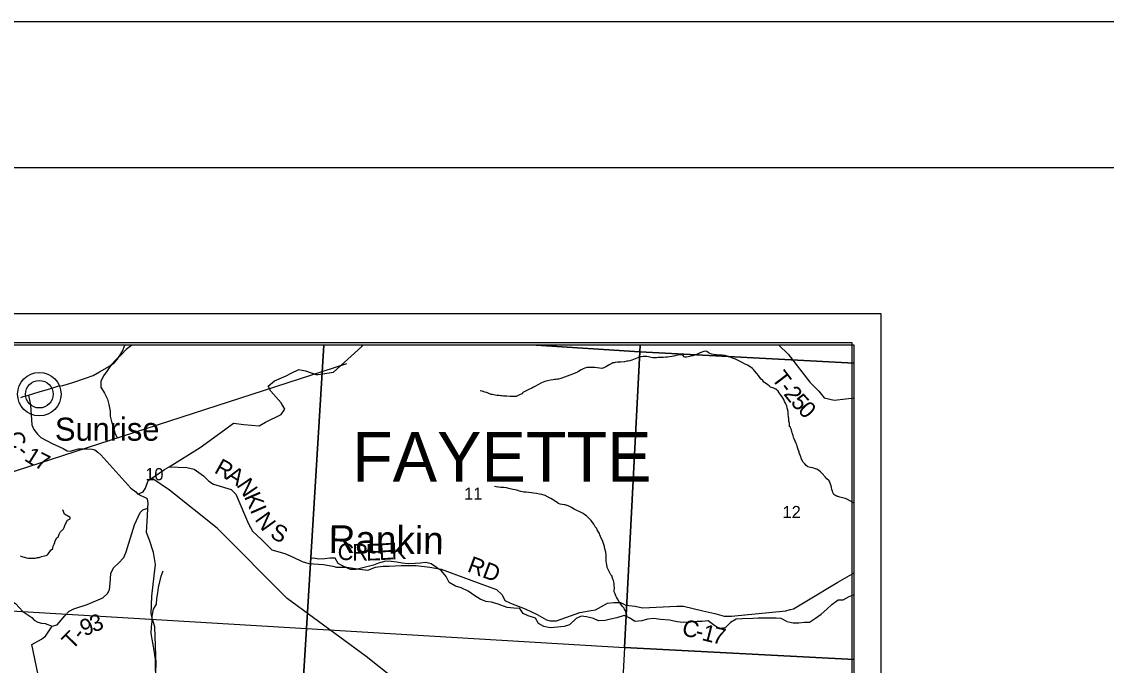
# Model space of a CAD drawing. Extents: x 0 to 34, y 0 to 22.
# Drawn here: x 6.056 to 9.772, y 19.794 to 22 of the extents above; entities that cross this region are included whole.
import ezdxf

# ---------------------------------------------------------------- set-up
doc = ezdxf.new("R2010")
doc.units = 0
for name, color, linetype in [('GM_X_County', 7, 'Continuous'), ('GM_X_County_Road', 7, 'Continuous'), ('GM_X_County_Road_Text', 7, 'Continuous'), ('GM_X_Minor_River', 7, 'Continuous'), ('GM_X_Minor_River_Text', 7, 'Continuous'), ('GM_X_Section', 7, 'Continuous'), ('GM_X_Section_Text', 7, 'Continuous'), ('GM_X_State_Route', 7, 'Continuous'), ('GM_X_Township', 7, 'Continuous'), ('GM_X_Township_Road', 7, 'Continuous'), ('GM_X_Township_Road_Text', 7, 'Continuous'), ('GM_X_Township_ROW', 7, 'Continuous'), ('GM_X_Township_Text', 7, 'Continuous'), ('GM_X_Unincorporated', 7, 'Continuous'), ('GM_X_Unincorporated_Location', 7, 'Continuous'), ('GM_X_Unincorporated_Text', 7, 'Continuous'), ('GM_X_US_Route', 7, 'Continuous'), ('SH_Border', 7, 'Continuous'), ('SH_Cut_Line', 7, 'Continuous'), ('SH_Data', 7, 'Continuous')]:
    doc.layers.add(name, color=color, linetype=linetype)

msp = doc.modelspace()

# ---------------------------------------------------------------- linework, layer by layer
at = {"layer": 'GM_X_County'}
msp.add_lwpolyline([(8.9084, 15.63), (8.9084, 20.8908), (2.1084, 20.8908), (2.1084, 19.9847)], dxfattribs=at)
at = {"layer": 'GM_X_County_Road'}
for points in [[(6.0801, 20.7202), (6.0863, 20.6856), (6.0907, 20.6183), (6.098, 20.6017), (6.1099, 20.5867), (6.1223, 20.5747), (6.1612, 20.5542), (6.1985, 20.537), (6.212, 20.5297), (6.2223, 20.5284), (6.2514, 20.5358), (6.2809, 20.5358), (6.298, 20.5354), (6.307, 20.5328), (6.3168, 20.5251), (6.3277, 20.5153), (6.4298, 20.4016), (6.4468, 20.3888), (6.4546, 20.3811), (6.4725, 20.3888), (6.4764, 20.3948), (6.477, 20.3957)], [(6.477, 20.3957), (6.481, 20.4016), (6.4895, 20.4272), (6.5017, 20.4356), (6.545, 20.4656), (6.5621, 20.4742), (6.6216, 20.4724), (6.6469, 20.466), (6.6786, 20.4438), (6.6976, 20.4248), (6.7135, 20.4153), (6.7737, 20.3963), (6.7895, 20.3805), (6.8339, 20.2791), (6.8465, 20.2538), (6.8782, 20.2253), (6.8972, 20.2063), (6.9131, 20.1904), (6.9574, 20.1777), (6.986, 20.1651), (7.0177, 20.1493), (7.0398, 20.1429), (7.0905, 20.1397), (7.1222, 20.1334), (7.1349, 20.1302), (7.1697, 20.1302), (7.2141, 20.1239), (7.2426, 20.1207), (7.268, 20.1302), (7.2933, 20.1334), (7.3155, 20.1334), (7.3567, 20.1365), (7.4074, 20.1365), (7.4549, 20.1302), (7.493, 20.1239), (7.6197, 20.0763), (7.6831, 20.0542), (7.7021, 20.0352), (7.7116, 20.0162), (7.7306, 20.0066), (7.7813, 19.9876), (7.8225, 19.9686), (7.8542, 19.9496), (7.8669, 19.9465), (7.8891, 19.9464), (7.9683, 19.975), (8, 19.9813), (8.0221, 19.9845), (8.0633, 20.0066), (8.0855, 20.0098), (8.1077, 20.0098), (8.1267, 20.0003), (8.1584, 19.9971), (8.1837, 19.9908), (8.301, 19.9971), (8.3232, 19.9971), (8.3897, 19.9813), (8.4309, 19.9718), (8.4626, 19.9622), (8.4879, 19.9622), (8.5228, 19.9654), (8.6741, 19.981), (8.6894, 19.9849), (8.6898, 19.985)], [(6.5144, 19.7584), (6.5165, 19.7955), (6.5124, 19.9254), (6.5041, 19.9522), (6.5, 19.9708), (6.5021, 20.0306), (6.5103, 20.1007), (6.5145, 20.1399), (6.5083, 20.1811), (6.4938, 20.2224), (6.4835, 20.2492), (6.4877, 20.3069), (6.4889, 20.3331), (6.4897, 20.3502), (6.4877, 20.3647), (6.4546, 20.3811)], [(8.6898, 19.985), (8.701, 19.9878), (8.7464, 20.0156), (8.852, 20.0788), (8.9084, 20.1115)]]:
    msp.add_lwpolyline(points, dxfattribs=at)
at = {"layer": 'GM_X_Minor_River'}
for points in [[(6.4328, 20.8908), (6.4327, 20.8907), (6.4144, 20.8764), (6.3985, 20.859), (6.381, 20.8431), (6.3627, 20.8234), (6.349, 20.8037), (6.3368, 20.7863), (6.3269, 20.7666), (6.3276, 20.7476), (6.3404, 20.7271), (6.3501, 20.7058), (6.3553, 20.6876), (6.3598, 20.6655), (6.3597, 20.6481), (6.3642, 20.6299), (6.3709, 20.6086), (6.3754, 20.5896), (6.3829, 20.5744)], [(8.6519, 20.7275), (8.6475, 20.7336), (8.64, 20.7406), (8.6329, 20.7434), (8.6257, 20.7462), (8.622, 20.7477), (8.6182, 20.7505), (8.6126, 20.7551), (8.6044, 20.7613), (8.5992, 20.7648), (8.5958, 20.7698), (8.5899, 20.7749), (8.585, 20.7803), (8.581, 20.7868), (8.5754, 20.7945), (8.5684, 20.8026), (8.5636, 20.808), (8.5598, 20.8115), (8.5516, 20.8173), (8.5434, 20.8224), (8.5328, 20.8275), (8.5223, 20.833), (8.5133, 20.8381), (8.5017, 20.8432), (8.4915, 20.8472), (8.484, 20.85), (8.4776, 20.852), (8.4738, 20.8532), (8.4693, 20.8548), (8.4659, 20.8556), (8.4599, 20.8564), (8.4553, 20.8569), (8.4512, 20.8574), (8.4451, 20.8571), (8.4398, 20.8575), (8.4364, 20.8576), (8.4323, 20.8584), (8.427, 20.8589), (8.4206, 20.8605), (8.4168, 20.8621), (8.4119, 20.8641), (8.4078, 20.8664), (8.4037, 20.8696), (8.3988, 20.8708), (8.3938, 20.8701), (8.387, 20.8676), (8.3786, 20.8643), (8.3747, 20.8621), (8.3702, 20.8599), (8.366, 20.8577), (8.3591, 20.8555), (8.3553, 20.8548), (8.3485, 20.8534), (8.3439, 20.8523), (8.3401, 20.8513), (8.3344, 20.8506), (8.3291, 20.8507), (8.3257, 20.8511), (8.3224, 20.8561), (8.319, 20.8585), (8.3148, 20.8585), (8.3095, 20.8579), (8.3038, 20.8568), (8.2977, 20.8554), (8.2905, 20.854), (8.2685, 20.8498), (8.2636, 20.8499), (8.2548, 20.8493), (8.2476, 20.8491), (8.2438, 20.8487), (8.2374, 20.8485), (8.2309, 20.8478), (8.2264, 20.8475), (8.2219, 20.848), (8.2185, 20.8484), (8.2124, 20.8493), (8.2034, 20.8513), (8.1977, 20.8522), (8.1916, 20.853), (8.1856, 20.8528), (8.178, 20.851), (8.17, 20.8489), (8.1528, 20.8423), (8.1463, 20.8398), (8.1402, 20.838), (8.1342, 20.8366), (8.1296, 20.8359), (8.1212, 20.8345), (8.1087, 20.8328), (8.0974, 20.8326), (8.0894, 20.832), (8.0856, 20.8313), (8.0818, 20.8302), (8.078, 20.8284), (8.0715, 20.8247), (8.0581, 20.817), (8.0508, 20.8137), (8.0443, 20.8115), (8.0364, 20.8124), (8.0194, 20.8146), (7.9993, 20.8145)], [(7.9993, 20.8145), (7.9929, 20.8143), (7.986, 20.8125), (7.9799, 20.8099), (7.973, 20.8063), (7.9642, 20.8011), (7.9608, 20.7993), (7.9547, 20.7963), (7.9463, 20.7927), (7.9348, 20.7883), (7.9257, 20.7847), (7.9162, 20.7818), (7.9032, 20.7775), (7.8956, 20.7753), (7.8922, 20.7746), (7.8876, 20.7739), (7.8815, 20.7733), (7.877, 20.7726), (7.8675, 20.7716), (7.858, 20.7695), (7.8485, 20.7666), (7.837, 20.7619), (7.8248, 20.7549), (7.8164, 20.7505), (7.8103, 20.7475), (7.8038, 20.7442), (7.7938, 20.7394), (7.782, 20.734), (7.7778, 20.7317), (7.7736, 20.7292), (7.7712, 20.725), (7.7644, 20.7221), (7.7544, 20.7173), (7.7502, 20.7159), (7.7442, 20.7156), (7.7392, 20.7153), (7.7294, 20.7151), (7.718, 20.7161), (7.712, 20.7169), (7.7071, 20.717), (7.7025, 20.7175), (7.6984, 20.7179), (7.6919, 20.7184), (7.687, 20.7189), (7.6836, 20.7193), (7.6783, 20.7198), (7.6742, 20.7206), (7.6685, 20.7218), (7.6651, 20.7227), (7.6572, 20.7254), (7.6527, 20.7274), (7.6482, 20.7286), (7.6429, 20.7306), (7.6343, 20.7334), (7.6267, 20.7351)], [(8.9084, 20.3491), (8.9055, 20.3515), (8.8957, 20.3562), (8.886, 20.362), (8.8788, 20.366), (8.8736, 20.3672), (8.869, 20.3684), (8.8596, 20.3705), (8.854, 20.3721), (8.8506, 20.3729), (8.8468, 20.3745), (8.8427, 20.3768), (8.8389, 20.3792), (8.8349, 20.3868), (8.8346, 20.3906), (8.832, 20.3964), (8.831, 20.4036), (8.83, 20.4089), (8.8278, 20.415), (8.826, 20.4185), (8.8227, 20.4261), (8.8149, 20.4331), (8.809, 20.4404), (8.7993, 20.4512), (8.793, 20.4574), (8.7877, 20.4617), (8.7825, 20.4652), (8.7761, 20.4676), (8.7723, 20.4691), (8.7667, 20.4704), (8.7584, 20.4724), (8.7501, 20.4748), (8.7445, 20.4784), (8.7389, 20.4841), (8.7337, 20.4903), (8.7297, 20.498), (8.7267, 20.5041), (8.7253, 20.5087), (8.7231, 20.5144), (8.7203, 20.5228), (8.7199, 20.5266), (8.7177, 20.5304), (8.7156, 20.5373), (8.7127, 20.5453), (8.7116, 20.5495), (8.7094, 20.5538), (8.7062, 20.5618), (8.7033, 20.5698), (8.7011, 20.5748), (8.6997, 20.5813), (8.6965, 20.5908), (8.695, 20.5958), (8.6932, 20.6011), (8.6914, 20.6057), (8.6907, 20.6099), (8.687, 20.6122), (8.6871, 20.6191), (8.6864, 20.6236), (8.6847, 20.6309), (8.6841, 20.6396), (8.6838, 20.6434), (8.6835, 20.6484), (8.6828, 20.6525), (8.6822, 20.6605), (8.6819, 20.6643), (8.6805, 20.6716), (8.6794, 20.6754), (8.6772, 20.6819), (8.6769, 20.6853), (8.6729, 20.6922), (8.6703, 20.6983), (8.667, 20.7048), (8.6615, 20.7137), (8.6574, 20.7194), (8.6549, 20.7236), (8.6519, 20.7275)], [(8.1297, 19.9598), (8.1298, 19.9647), (8.128, 19.9724), (8.1262, 19.9766), (8.1248, 19.9804), (8.1214, 19.9854), (8.1204, 19.9896), (8.1141, 19.9965), (8.107, 20.0065), (8.103, 20.0119), (8.0975, 20.0222), (8.0938, 20.028), (8.0916, 20.0322), (8.0891, 20.0395), (8.0865, 20.046), (8.0862, 20.0494), (8.0868, 20.0589), (8.0862, 20.0672), (8.0859, 20.0729), (8.0845, 20.0802), (8.0842, 20.0844), (8.0816, 20.0897), (8.0791, 20.0966), (8.0788, 20.1), (8.0751, 20.1043), (8.0725, 20.1089), (8.0674, 20.1184), (8.0644, 20.1246), (8.0626, 20.1295), (8.0605, 20.1391), (8.0602, 20.1436), (8.0588, 20.1512), (8.0582, 20.16), (8.0585, 20.1717), (8.0571, 20.1813), (8.0547, 20.1931), (8.0529, 20.2015), (8.0497, 20.211), (8.0457, 20.2213), (8.0421, 20.2297), (8.0366, 20.2416), (8.0355, 20.2462), (8.0278, 20.2585), (8.0271, 20.2626), (8.0215, 20.2692), (8.016, 20.2776), (8.0075, 20.2899), (7.9982, 20.3), (7.9911, 20.3062), (7.9855, 20.3101), (7.9803, 20.3139), (7.9683, 20.3202), (7.9585, 20.3249), (7.9495, 20.3289), (7.9405, 20.3351), (7.9352, 20.3375), (7.9285, 20.341), (7.9251, 20.3422), (7.9217, 20.3434), (7.9183, 20.3439), (7.9145, 20.3443), (7.9085, 20.3452), (7.9017, 20.3464), (7.896, 20.3484), (7.8919, 20.3511), (7.8837, 20.357), (7.8785, 20.3605), (7.8751, 20.3624), (7.8695, 20.3656), (7.8605, 20.3707), (7.8492, 20.3762), (7.8379, 20.379), (7.83, 20.3811), (7.8198, 20.3827), (7.8096, 20.3841), (7.8031, 20.3853), (7.7937, 20.3862), (7.7846, 20.3871), (7.7767, 20.388), (7.7725, 20.3889), (7.7665, 20.3901), (7.7589, 20.3918), (7.7556, 20.393), (7.7469, 20.395), (7.7393, 20.397), (7.7341, 20.3983), (7.7258, 20.3999), (7.7175, 20.402), (7.7073, 20.4033), (7.6974, 20.4034), (7.6823, 20.406), (7.6762, 20.4065)], [(6.0505, 20.1695), (6.0569, 20.1671), (6.0603, 20.1659), (6.066, 20.1643), (6.0697, 20.1631), (6.0731, 20.1622), (6.0788, 20.161), (6.0909, 20.1608), (6.0958, 20.1611), (6.1038, 20.1617), (6.1106, 20.1631), (6.1156, 20.1638), (6.124, 20.1671), (6.1342, 20.1688), (6.1403, 20.1702), (6.1445, 20.1732), (6.1484, 20.1773), (6.1565, 20.1882), (6.1631, 20.1945), (6.1644, 20.2025), (6.1671, 20.2093), (6.1695, 20.2145), (6.1704, 20.2202), (6.177, 20.2307), (6.1808, 20.2333), (6.1844, 20.2432), (6.1876, 20.2503), (6.1957, 20.2585), (6.1999, 20.2619), (6.2019, 20.2668), (6.2027, 20.2702), (6.2054, 20.2762), (6.2137, 20.2916), (6.2221, 20.2957), (6.2218, 20.3002), (6.203, 20.3123), (6.1976, 20.3269)], [(8.6773, 19.9438), (8.6584, 19.9549), (8.641, 19.9558), (8.5796, 19.956), (8.5615, 19.9545), (8.5251, 19.9531), (8.5039, 19.9517), (8.4849, 19.9412), (8.4659, 19.923), (8.4485, 19.92), (8.4311, 19.9292), (8.4077, 19.946), (8.388, 19.9445), (8.3706, 19.9446), (8.3486, 19.9424), (8.3228, 19.941), (8.3016, 19.9433), (8.2759, 19.9488), (8.2449, 19.9511), (8.2222, 19.9543), (8.2002, 19.9521), (8.1812, 19.9468), (8.1585, 19.9439), (8.1373, 19.9569), (8.12, 19.9645), (8.0957, 19.957), (8.0737, 19.9518), (8.0548, 19.9481), (8.0328, 19.9466), (8.0154, 19.955), (7.9912, 19.9604), (7.973, 19.962), (7.9556, 19.9545), (7.9335, 19.9333), (7.9153, 19.9266), (7.8918, 19.9244), (7.8668, 19.9222), (7.8456, 19.9268), (7.8267, 19.9375), (7.817, 19.9558), (7.792, 19.9634), (7.7746, 19.9711), (7.7626, 19.9886), (7.7429, 19.9902), (7.7194, 19.9926), (7.6892, 20.0033), (7.6657, 20.0102), (7.6468, 20.0126), (7.6272, 20.021), (7.609, 20.0317), (7.5864, 20.0485), (7.5622, 20.0592), (7.5425, 20.0653), (7.5214, 20.0783), (7.5101, 20.0981), (7.4943, 20.1179), (7.4769, 20.1293), (7.4588, 20.1423), (7.4406, 20.1469), (7.4217, 20.1447), (7.4042, 20.1425), (7.3815, 20.1418), (7.3603, 20.1442), (7.3414, 20.1473), (7.3217, 20.1496), (7.3036, 20.1505), (7.2793, 20.1437), (7.2611, 20.1377), (7.2391, 20.1317), (7.2209, 20.1272), (7.202, 20.122), (7.183, 20.1228), (7.1581, 20.1335), (7.1407, 20.1427), (7.1302, 20.161), (7.112, 20.161), (7.0946, 20.1588), (7.0741, 20.1581), (7.0567, 20.1612), (7.0446, 20.1605)], [(6.5151, 19.7738), (6.5152, 19.795), (6.5145, 19.814), (6.5116, 19.8376), (6.5079, 19.8588), (6.5034, 19.8839), (6.4997, 19.9044), (6.5006, 19.9264), (6.5029, 19.9446), (6.5038, 19.9628), (6.5084, 19.9864), (6.5176, 20.0038), (6.5192, 20.0228), (6.523, 20.0425), (6.5254, 20.0607), (6.5292, 20.0797), (6.5346, 20.0994), (6.5408, 20.1176)], [(8.6773, 19.9438), (8.6992, 19.9392), (8.7189, 19.9392), (8.7378, 19.9415), (8.7552, 19.9422), (8.7764, 19.9551), (8.7954, 19.9695), (8.8143, 19.9869), (8.8318, 20.0029), (8.8538, 20.0188), (8.8712, 20.0188), (8.8916, 20.0301), (8.9084, 20.0372)]]:
    msp.add_lwpolyline(points, dxfattribs=at)
at = {"layer": 'GM_X_Section'}
for p, q in [((7.0909, 20.8908), (5.9857, 20.8908)), ((7.8185, 20.8908), (7.0909, 20.8908)), ((8.1758, 20.8908), (7.8185, 20.8908)), ((8.9084, 19.8145), (8.9084, 20.8291)), ((8.9084, 18.7841), (8.9084, 19.8145))]:
    msp.add_line(p, q, dxfattribs=at)
for points in [[(5.9857, 20.8908), (5.9246, 19.9867), (7.0324, 19.92), (7.0909, 20.8908)], [(7.0909, 20.8908), (7.0324, 19.92), (8.1212, 19.8553), (8.1746, 20.8684), (7.8185, 20.8908)], [(7.8185, 20.8908), (8.1746, 20.8684), (8.1758, 20.8908)], [(8.1758, 20.8908), (8.1746, 20.8684), (8.9084, 20.8291)], [(8.9084, 20.8291), (8.9084, 20.8908), (8.1758, 20.8908)], [(8.9084, 20.8291), (8.1746, 20.8684), (8.1212, 19.8553), (8.9084, 19.8145)], [(8.9084, 19.8145), (8.1212, 19.8553), (8.0664, 18.8297), (8.9084, 18.7841)]]:
    msp.add_lwpolyline(points, dxfattribs=at)
for points in [[(7.0324, 19.92), (6.9681, 18.8952), (5.8561, 18.9573), (5.9246, 19.9867)], [(8.1212, 19.8553), (8.0664, 18.8297), (6.9681, 18.8952), (7.0324, 19.92)]]:
    msp.add_lwpolyline(points, close=True, dxfattribs=at)
at = {"layer": 'GM_X_State_Route'}
msp.add_lwpolyline([(6.0532, 20.7119), (6.0615, 20.7151), (6.0801, 20.7202), (6.094, 20.7249), (6.1199, 20.7326), (6.1444, 20.7395), (6.1805, 20.7505), (6.1971, 20.753), (6.2313, 20.7633), (6.2753, 20.7784), (6.3007, 20.7879), (6.3233, 20.7997), (6.3574, 20.8191), (6.3733, 20.8309), (6.3844, 20.8436), (6.4013, 20.8704), (6.4096, 20.8908)], dxfattribs=at)
at = {"layer": 'GM_X_Township'}
msp.add_lwpolyline([(8.9084, 15.63), (8.9084, 20.8908), (5.9855, 20.8908)], dxfattribs=at)
at = {"layer": 'GM_X_Township_Road'}
for points in [[(6.5621, 20.4742), (6.6677, 20.54), (6.7513, 20.6015), (6.782, 20.6235), (6.8172, 20.6191), (6.87, 20.6147), (6.892, 20.6279), (6.9448, 20.6542), (6.958, 20.6718), (6.9448, 20.6938), (6.9096, 20.7334), (6.9008, 20.751), (6.9228, 20.7686), (6.9624, 20.7861), (6.98, 20.7949), (7.0063, 20.8081), (7.0283, 20.8037), (7.0635, 20.7905), (7.0723, 20.7905), (7.1251, 20.7993), (7.2218, 20.8872), (7.2252, 20.8908)], [(8.6505, 20.8908), (8.6819, 20.8607), (8.7567, 20.764), (8.7875, 20.7332), (8.8051, 20.7112), (8.8403, 20.7024), (8.8798, 20.7068), (8.9084, 20.7104)], [(6.1299, 19.8887), (6.1377, 19.8944), (6.161, 19.9285), (6.1782, 19.9331), (6.204, 19.9631), (6.2184, 19.9798), (6.2354, 19.9881), (6.2805, 20.0022), (6.3339, 20.0257), (6.3498, 20.0405), (6.357, 20.0526), (6.3597, 20.0746), (6.3612, 20.1092), (6.3711, 20.1281), (6.3885, 20.1441), (6.4063, 20.1634), (6.4142, 20.1832), (6.4431, 20.275), (6.462, 20.3179), (6.4718, 20.3274), (6.4889, 20.3331)], [(5.9309, 20.0406), (5.9309, 20.0405), (5.9563, 20.0273), (5.979, 20.0197), (5.9975, 20.0201), (6.0165, 20.0178), (6.0347, 20.0064), (6.06, 19.9787), (6.0911, 19.9578), (6.0987, 19.9491), (6.1112, 19.9419), (6.1237, 19.9385), (6.1362, 19.9369), (6.161, 19.9285)]]:
    msp.add_lwpolyline(points, dxfattribs=at)
at = {"layer": 'GM_X_Township_ROW'}
for points in [[(7.4921, 19.6213), (7.2363, 19.8245), (6.9655, 20.0235), (6.7261, 20.2643), (6.563, 20.3945), (6.5017, 20.4356)], [(6.1894, 19.3332), (6.1876, 19.3562), (6.1898, 19.3892), (6.0906, 19.8649), (6.1237, 19.8842), (6.1299, 19.8887)]]:
    msp.add_lwpolyline(points, dxfattribs=at)
at = {"layer": 'GM_X_Unincorporated'}
for radius in [0.0744, 0.0472]:
    msp.add_circle((6.1167, 20.7233), radius, dxfattribs=at)
at = {"layer": 'GM_X_Unincorporated_Location'}
msp.add_line((6.1167, 20.7233), (6.1167, 20.7233), dxfattribs=at)
at = {"layer": 'GM_X_US_Route'}
msp.add_lwpolyline([(7.1693, 20.827), (4.6185, 20.0016)], dxfattribs=at)
at = {"layer": 'SH_Border'}
msp.add_lwpolyline([(1.5, 21.5), (33.5, 21.5), (33.5, 0.5), (1.5, 0.5)], close=True, dxfattribs=at)
at = {"layer": 'SH_Cut_Line'}
msp.add_lwpolyline([(0, 0), (34, 0), (34, 22), (0, 22)], close=True, dxfattribs=at)
at = {"layer": 'SH_Data'}
for p, q in [((2, 21), (9, 21)), ((9, 21), (9, 14)), ((2.1, 20.9), (8.9, 20.9)), ((8.9, 20.9), (8.9, 14.1))]:
    msp.add_line(p, q, dxfattribs=at)

# ---------------------------------------------------------------- texts
at = {"layer": 'GM_X_County_Road_Text'}
for s, height, rotation, p in [('C', 0.0568, 298.2217, (6.0011, 20.5782)), ('-', 0.0568, 316.97, (6.0355, 20.5211)), ('1', 0.0568, 327.8251, (6.0619, 20.498)), ('7', 0.0568, 333.1217, (6.0965, 20.4765)), ('R', 0.0568, 330.78, (6.7128, 20.4559)), ('A', 0.0568, 327.6869, (6.7528, 20.4335)), ('N', 0.0568, 304.025, (6.7906, 20.4111)), ('K', 0.0568, 293.6398, (6.8173, 20.372)), ('I', 0.0568, 293.5955, (6.8373, 20.3263)), ('N', 0.0568, 305.5773, (6.8531, 20.2936)), ('S', 0.0568, 332.127, (6.9036, 20.2342)), ('K', 0.0568, 1.9164, (7.3237, 20.157)), ('C', 0.0568, 354.6277, (7.1364, 20.1576)), ('R', 0.0568, 359.9039, (7.1885, 20.153)), ('E', 0.0568, 1.6911, (7.2371, 20.1529)), ('E', 0.0568, 3.7194, (7.2818, 20.1543)), ('RD', 0.05682, 339.3866, (7.5797, 20.1165)), ('C', 0.0568, 345.0772, (8.3147, 19.899)), ('1', 0.0568, 345.5731, (8.3837, 19.8812)), ('7', 0.0568, 346.8992, (8.419, 19.8722)), ('-', 0.0568, 346.4803, (8.3612, 19.8866))]:
    msp.add_text(s, height=height, rotation=rotation, dxfattribs=at).set_placement(p)
at = {"layer": 'GM_X_Minor_River_Text'}
msp.add_text('Rankin', height=0.09469, rotation=359.2425, dxfattribs=at).set_placement((7.1073, 20.1796))
at = {"layer": 'GM_X_Section_Text'}
for s, p in [('10', (6.4798, 20.4281)), ('11', (7.5723, 20.3614)), ('12', (8.6631, 20.2984))]:
    msp.add_text(s, height=0.04186, rotation=0, dxfattribs=at).set_placement(p)
at = {"layer": 'GM_X_Township_Road_Text'}
for s, rotation, p in [('T', 307.2374, (8.6233, 20.7768)), ('-', 307.6766, (8.6493, 20.7426)), ('2', 308.9803, (8.6645, 20.723)), ('5', 311.694, (8.6884, 20.6935)), ('0', 313.4766, (8.713, 20.666)), ('9', 24.0758, (6.2713, 19.8919)), ('3', 21.212, (6.3026, 19.9059)), ('T', 45.45, (6.2286, 19.8445)), ('-', 49.6189, (6.2615, 19.8782))]:
    msp.add_text(s, height=0.0568, rotation=rotation, dxfattribs=at).set_placement(p)
at = {"layer": 'GM_X_Township_Text'}
msp.add_text('FAYETTE', height=0.17045, rotation=0, dxfattribs=at).set_placement((7.1882, 20.4234))
at = {"layer": 'GM_X_Unincorporated_Text'}
msp.add_text('Sunrise', height=0.07898, rotation=0, dxfattribs=at).set_placement((6.1702, 20.5638))

doc.saveas('drawing.dxf')
